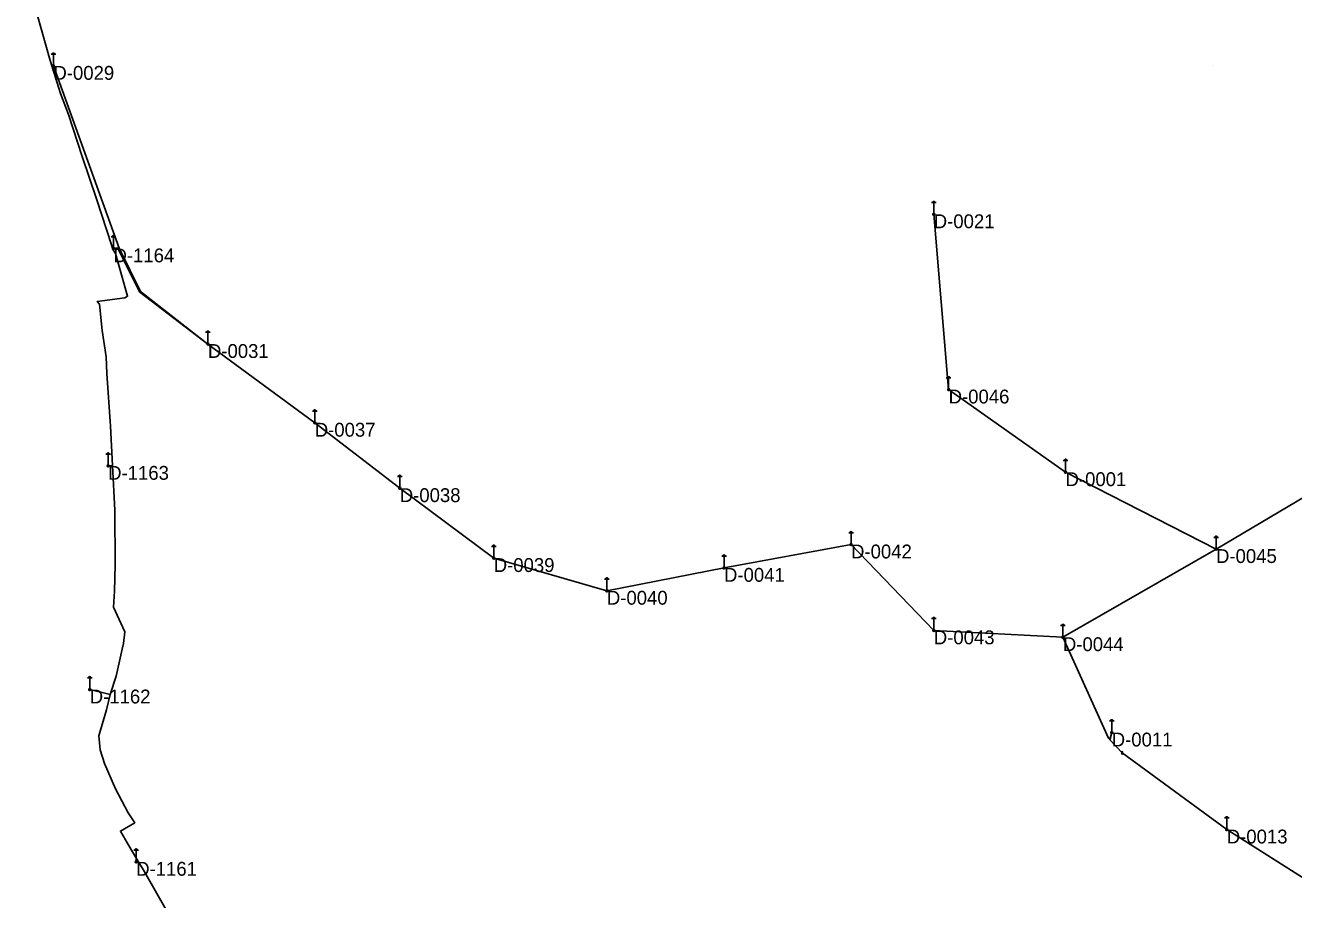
# Model space of a CAD drawing. Extents: x -729889 to -691139, y -995431 to -974354.
# Drawn here: x -727320.4 to -727045.7, y -977727.9 to -977538.5 of the extents above; entities that cross this region are included whole.
import ezdxf

# ---------------------------------------------------------------- set-up
doc = ezdxf.new("R2010")
doc.units = 0
for name, color, linetype in [('Atributy', 7, 'Continuous'), ('Dočasné zaměření bodu', 7, 'Continuous'), ('Kabelové vedení VO', 7, 'Continuous'), ('Skutečně zaměřené kabelové vedení', 7, 'Continuous'), ('Spojka kabelová', 7, 'Continuous'), ('Světelný bod na stožáru sadovém', 7, 'Continuous')]:
    doc.layers.add(name, color=color, linetype=linetype)

# ---------------------------------------------------------------- blocks, each defined once
blk = doc.blocks.new('POINT_DISPLAY')
blk.add_line((0, 0), (0, 0))
blk = doc.blocks.new('6.571')
at = {"layer": 'Světelný bod na stožáru sadovém'}
for p, q in [((-0.51, 2.54), (0.51, 2.54)), ((0, 2.54), (0, 0.2))]:
    blk.add_line(p, q, dxfattribs=at)
for points in [[(0.25, 2.54), (0.25, 2.56), (0.25, 2.58), (0.24, 2.6), (0.24, 2.62), (0.23, 2.64), (0.22, 2.66), (0.21, 2.69), (0.19, 2.7), (0.18, 2.72), (0.16, 2.73), (0.15, 2.75), (0.13, 2.76), (0.11, 2.77), (0.09, 2.78), (0.07, 2.78), (0.05, 2.79), (0.02, 2.79), (0, 2.79), (-0.02, 2.79), (-0.05, 2.79), (-0.07, 2.78), (-0.09, 2.78), (-0.11, 2.77), (-0.13, 2.76), (-0.15, 2.75), (-0.16, 2.73), (-0.18, 2.72), (-0.19, 2.7), (-0.21, 2.69), (-0.22, 2.66), (-0.23, 2.64), (-0.24, 2.62), (-0.24, 2.6), (-0.25, 2.58), (-0.25, 2.56), (-0.25, 2.54)], [(-0.2, 0), (-0.17, -0.1), (-0.08, -0.18), (0.04, -0.19), (0.13, -0.14), (0.19, -0.05), (0.18, 0.07), (0.12, 0.15), (0.02, 0.19), (-0.09, 0.17), (-0.17, 0.09), (-0.18, -0.01), (-0.15, -0.1), (-0.06, -0.17), (0.04, -0.17), (0.12, -0.12), (0.17, -0.03), (0.16, 0.08), (0.1, 0.14), (0.01, 0.17), (-0.09, 0.14), (-0.15, 0.07), (-0.16, -0.01), (-0.12, -0.1), (-0.04, -0.15), (0.04, -0.15), (0.12, -0.1), (0.15, -0.01), (0.14, 0.07), (0.08, 0.13), (-0.01, 0.15), (-0.09, 0.12), (-0.13, 0.06), (-0.14, -0.02), (-0.1, -0.1), (-0.03, -0.13), (0.04, -0.13), (0.11, -0.08), (0.13, 0), (0.12, 0.07), (0.06, 0.12), (-0.02, 0.13), (-0.08, 0.1), (-0.12, 0.05), (-0.12, -0.03), (-0.08, -0.09), (-0.02, -0.11), (0.05, -0.11), (0.1, -0.06), (0.11, 0.01), (0.1, 0.06), (0.05, 0.11), (-0.02, 0.11), (-0.07, 0.09), (-0.1, 0.04), (-0.1, -0.03), (-0.06, -0.08), (-0.02, -0.1), (0.05, -0.08), (0.09, -0.04), (0.1, 0.01), (0.08, 0.06), (0.03, 0.09), (-0.02, 0.09), (-0.06, 0.07), (-0.08, 0.02), (-0.08, -0.03), (-0.05, -0.06), (-0.01, -0.08), (0.04, -0.06), (0.07, -0.03), (0.07, 0.01), (0.06, 0.05), (0.02, 0.07), (-0.02, 0.07), (-0.05, 0.05), (-0.07, 0.02), (-0.06, -0.03), (-0.04, -0.05), (0, -0.06), (0.04, -0.04), (0.05, -0.02), (0.06, 0.01), (0.04, 0.04), (0.01, 0.05), (-0.02, 0.05), (-0.04, 0.04), (-0.05, 0.01), (-0.04, -0.02), (-0.02, -0.03), (0.01, -0.04), (0.03, -0.03), (0.04, -0.01), (0.04, 0.01), (0.02, 0.03), (0.01, 0.04), (-0.01, 0.03), (-0.02, 0.02), (-0.03, 0.01), (-0.02, -0.01), (-0.01, -0.02)], [(-0.01, -0.02), (0.01, -0.02), (0.01, -0.01), (0.02, 0), (0.02, 0.01), (0.01, 0.02), (0, 0.02), (-0.01, 0.01), (-0.01, 0.01), (-0.01, 0.01)]]:
    blk.add_lwpolyline(points, dxfattribs=at)
blk.add_circle((0, 0), 0.203, dxfattribs=at)
blk = doc.blocks.new('4.0200_BB')
at = {"layer": 'Spojka kabelová'}
blk.add_lwpolyline([(-0.02, 0.01), (-0.02, 0.17), (-0.1, 0.17), (-0.1, 0.21), (-0.02, 0.21), (-0.02, 0.28), (0.02, 0.28), (0.02, 0.21), (0.11, 0.21), (0.11, 0.17), (0.02, 0.17), (0.02, 0.01)], close=True, dxfattribs=at)
for radius in [0.15, 0.0945]:
    blk.add_circle((0, -0.13), radius, dxfattribs=at)

msp = doc.modelspace()

# ---------------------------------------------------------------- linework, layer by layer
at = {"layer": 'Kabelové vedení VO'}
for p, q in [((-727123.67, -977579.42), (-727120.45, -977617.38)), ((-727280.85, -977607.52), (-727257.72, -977624.57)), ((-727095.13, -977635.28), (-727120.45, -977617.38)), ((-727257.72, -977624.57), (-727239.31, -977638.74)), ((-727095.13, -977635.28), (-727062.54, -977651.93)), ((-727033.63, -977634.78), (-727062.54, -977651.93)), ((-727239.31, -977638.74), (-727218.96, -977653.88)), ((-727169.09, -977656), (-727141.58, -977650.94)), ((-727141.58, -977650.94), (-727123.66, -977669.54)), ((-727095.7, -977671.02), (-727062.54, -977651.93)), ((-727218.96, -977653.88), (-727194.46, -977660.96)), ((-727194.46, -977660.96), (-727169.09, -977656)), ((-727123.66, -977669.54), (-727095.7, -977671.02)), ((-727060.22, -977712.68), (-727038.65, -977726.33))]:
    msp.add_line(p, q, dxfattribs=at)
for points in [[(-727280.85, -977607.52), (-727295.46, -977596.16), (-727300.09, -977586.77), (-727314.31, -977547.28)], [(-727280.85, -977607.52), (-727295.58, -977596.29), (-727300.44, -977586.66), (-727301.3, -977586.81)], [(-727095.7, -977671.02), (-727085.84, -977692.86), (-727085.63, -977693.13), (-727085.5, -977693.04), (-727085.13, -977691.67)], [(-727085.13, -977691.67), (-727085.53, -977693.23), (-727082.86, -977696.04), (-727060.22, -977712.68)]]:
    msp.add_lwpolyline(points, dxfattribs=at)
at = {"layer": 'Skutečně zaměřené kabelové vedení'}
for points in [[(-727314.61, -977547.51), (-727315.02, -977546.1), (-727317.86, -977536.15), (-727320.12, -977527.17), (-727320.39, -977524.44), (-727318.93, -977521.02), (-727316.08, -977517.47), (-727310.59, -977514.11), (-727307.62, -977512.5), (-727305.37, -977511.41), (-727302.33, -977509.82), (-727302.66, -977508.8), (-727308.62, -977498.01), (-727310.73, -977479.95)], [(-727314.31, -977547.28), (-727314.61, -977547.51), (-727315.02, -977546.1), (-727317.86, -977536.15), (-727320.12, -977527.17), (-727320.39, -977524.44), (-727318.93, -977521.02), (-727317.68, -977518.63), (-727316.37, -977518.02), (-727315.58, -977518.29)], [(-727301.53, -977586.89), (-727301.7, -977586.27), (-727305.02, -977576.1), (-727308.08, -977566.92), (-727311.05, -977557.83), (-727312.79, -977553.28), (-727314.61, -977547.51), (-727314.31, -977547.28)], [(-727301.53, -977633.86), (-727301.96, -977625.33), (-727302.72, -977613.89), (-727302.91, -977610.3), (-727303.74, -977604.55), (-727304.31, -977598.9), (-727304.82, -977598.29), (-727298.83, -977597.51), (-727298.25, -977597.16), (-727300.9, -977587.93), (-727301.53, -977586.89), (-727301.3, -977586.81)], [(-727302.04, -977683.39), (-727300.76, -977679.48), (-727299.43, -977673.61), (-727299.13, -977672.41), (-727298.86, -977669.84), (-727301.31, -977664.49), (-727301.09, -977661.05), (-727300.91, -977655.36), (-727301.05, -977643.51), (-727301.53, -977633.86), (-727302.46, -977633.91)], [(-727296.02, -977719.44), (-727298.16, -977715.9), (-727299.82, -977713), (-727296.71, -977711.21), (-727298.1, -977709.05), (-727300.85, -977703.82), (-727303.26, -977698.39), (-727304.22, -977695.43), (-727304.5, -977692.38), (-727302.84, -977686.77), (-727302.04, -977683.39), (-727306.45, -977682.35)], [(-727268.46, -977758), (-727271.53, -977753.83), (-727273.26, -977751.6), (-727279.15, -977745.07), (-727285.26, -977738.54), (-727286.86, -977736.27), (-727289.31, -977731.06), (-727294.89, -977721.32), (-727296.02, -977719.44), (-727296.39, -977719.66)]]:
    msp.add_lwpolyline(points, dxfattribs=at)

# ---------------------------------------------------------------- block references
at = {"layer": 'Dočasné zaměření bodu'}
msp.add_blockref('POINT_DISPLAY', (-727063.21, -977547.13), dxfattribs=at)
at = {"layer": 'Spojka kabelová'}
msp.add_blockref('4.0200_BB', (-727082.86, -977696.04), dxfattribs=at)
at = {"layer": 'Světelný bod na stožáru sadovém', "xscale": 1.0016949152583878, "yscale": 1.0016949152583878}
for p in [(-727314.31, -977547.28), (-727123.67, -977579.42), (-727301.3, -977586.81), (-727280.85, -977607.52), (-727120.45, -977617.38), (-727257.72, -977624.57), (-727302.46, -977633.91), (-727095.13, -977635.28), (-727239.31, -977638.74), (-727141.58, -977650.94), (-727062.54, -977651.93), (-727218.96, -977653.88), (-727169.09, -977656), (-727194.46, -977660.96), (-727123.66, -977669.54), (-727095.7, -977671.02), (-727306.45, -977682.35), (-727085.13, -977691.67), (-727060.22, -977712.68), (-727296.39, -977719.66)]:
    msp.add_blockref('6.571', p, dxfattribs=at)

# ---------------------------------------------------------------- texts
at = {"layer": 'Atributy'}
for s, p in [('D-0029', (-727314.31, -977550.29)), ('D-0021', (-727123.67, -977582.43)), ('D-1164', (-727301.3, -977589.82)), ('D-0031', (-727280.85, -977610.53)), ('D-0046', (-727120.45, -977620.39)), ('D-0037', (-727257.72, -977627.58)), ('D-1163', (-727302.46, -977636.92)), ('D-0001', (-727095.13, -977638.29)), ('D-0038', (-727239.31, -977641.75)), ('D-0042', (-727141.58, -977653.95)), ('D-0045', (-727062.54, -977654.94)), ('D-0039', (-727218.96, -977656.89)), ('D-0041', (-727169.09, -977659.01)), ('D-0040', (-727194.46, -977663.97)), ('D-0043', (-727123.66, -977672.55)), ('D-0044', (-727095.7, -977674.03)), ('D-1162', (-727306.45, -977685.36)), ('D-0011', (-727085.13, -977694.68)), ('D-0013', (-727060.22, -977715.69)), ('D-1161', (-727296.39, -977722.67))]:
    msp.add_text(s, height=3, dxfattribs=at).set_placement(p)

doc.saveas('drawing.dxf')
